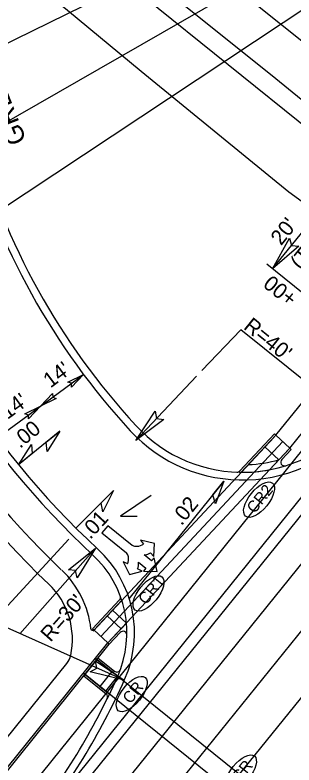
# Model space of a CAD drawing. Extents: x 1486489 to 1490134, y 497089 to 500876.
# Drawn here: x 1488642 to 1488715.1, y 499048.4 to 499245.3 of the extents above; entities that cross this region are included whole.
import ezdxf

# ---------------------------------------------------------------- set-up
doc = ezdxf.new("R2010")
doc.units = 0
for name, color, linetype in [('DEV PRELIMINARY STAMP CELL', 7, 'Continuous'), ('Gray Area Fill Shapes', 7, 'Continuous'), ('Pattern 5', 7, 'Continuous'), ('Prop DSN Text', 7, 'Continuous'), ('Prop Guardrail Anchor Unit CELL', 7, 'Continuous'), ('Prop Horizontal Alignment Station Label', 7, 'Continuous'), ('Prop North Arrow NAD83 for Plan Sheets CELL', 7, 'Continuous'), ('Prop Rem of Exist Asph Pvmt', 7, 'Continuous'), ('Prop Text', 7, 'Continuous'), ('Prop WCC CELL', 7, 'Continuous'), ('Scratch_Level_0', 7, 'Continuous'), ('Scratch_Level_5', 7, 'Continuous'), ('Sheet Block Revision CELL', 7, 'Continuous'), ('Sheet Block Title CELL', 7, 'Continuous'), ('Sheet Cutting Line CELL', 7, 'Continuous'), ('Sheet Data Field CELL', 7, 'Continuous'), ('Sheet Plan CELL', 7, 'Continuous'), ('Sheet Plot Border Inside CELL', 7, 'Continuous'), ('Sheet Plot Border Outside CELL', 7, 'Continuous'), ('Sheet Sticker Exception Certification CELL', 7, 'Continuous')]:
    doc.layers.add(name, color=color, linetype=linetype)

msp = doc.modelspace()

# ---------------------------------------------------------------- linework, layer by layer
at = {"layer": 'DEV PRELIMINARY STAMP CELL'}
for p, q in [((1488709.54, 499178.58), (1488722.09, 499194.15)), ((1488742.52, 499151.98), (1488707.98, 499179.84)), ((1488653.77, 499136.03), (1488642.91, 499127.2)), ((1488696.73, 499122.88), (1488671.81, 499091.97)), ((1488657.96, 499110.53), (1488667.84, 499120.45))]:
    msp.add_line(p, q, dxfattribs=at)
for points in [[(1488716.39, 499184.61), (1488709.54, 499178.58), (1488713.97, 499186.63), (1488714.49, 499184.73)], [(1488653.77, 499136.03), (1488650.38, 499130.69), (1488650.18, 499133.11)], [(1488642.91, 499127.2), (1488646.3, 499132.53), (1488646.5, 499130.12)], [(1488696.73, 499122.88), (1488694.52, 499116.95), (1488693.83, 499119.28)], [(1488667.84, 499120.45), (1488665.02, 499114.79), (1488664.58, 499117.17)]]:
    msp.add_lwpolyline(points, close=True, dxfattribs=at)
at = {"layer": 'Pattern 5'}
for p, q in [((1488708.74, 499125.87), (1488711.18, 499128.49)), ((1488703.19, 499127.24), (1488701.29, 499125.2)), ((1488667.55, 499089.02), (1488666.18, 499087.56)), ((1488671.2, 499085.62), (1488667.55, 499089.02)), ((1488666.18, 499087.56), (1488669.83, 499084.15)), ((1488669.83, 499084.15), (1488671.2, 499085.62))]:
    msp.add_line(p, q, dxfattribs=at)
msp.add_lwpolyline([(1488669.83, 499084.15), (1488669.83, 499084.15)], dxfattribs=at)
for radius, start, end in [(36, 272.4835, 285.3858), (38, 269.494, 280.7817)]:
    msp.add_arc((1488701.63, 499163.2), radius, start, end, dxfattribs=at)
at = {"layer": 'Prop DSN Text'}
for p, q in [((1488775.29, 499304.32), (1488416.25, 499127.99)), ((1488432.18, 499098.05), (1488779.08, 499297.19)), ((1488783.32, 499290.32), (1488450, 499069.19)), ((1488566.47, 498943.86), (1488817.57, 499255.22))]:
    msp.add_line(p, q, dxfattribs=at)
at = {"layer": 'Prop Horizontal Alignment Station Label'}
for p, q in [((1488710.38, 499134.95), (1488753.3, 499188.25)), ((1488714.03, 499131.55), (1488719.53, 499138.4)), ((1488710.38, 499134.95), (1488701.29, 499125.2)), ((1488714.03, 499131.55), (1488710.38, 499134.95)), ((1488711.18, 499128.49), (1488707.53, 499131.9)), ((1488714.03, 499131.55), (1488708.74, 499125.87)), ((1488662.74, 499083.86), (1488669.96, 499091.61)), ((1488671.2, 499085.62), (1488667.55, 499089.02)), ((1488669.83, 499084.15), (1488666.18, 499087.56)), ((1488666.32, 499080.39), (1488671.2, 499085.62)), ((1488666.33, 499080.4), (1488662.68, 499083.81)), ((1488627.75, 499032.57), (1488666.32, 499080.39)), ((1488623.86, 499035.7), (1488655.57, 499075.03))]:
    msp.add_line(p, q, dxfattribs=at)
for centre, radius, start, end in [((1488809.02, 499262.12), 224.5, 195.2846, 226.3706), ((1488809.02, 499262.12), 229.5, 195.2846, 226.422), ((1488701.63, 499163.2), 36, 272.4835, 285.3858), ((1488637.03, 499081.37), 25, 6.3813, 46.422), ((1488637.03, 499081.37), 20, 347.6839, 46.422), ((1488662.37, 499084.2), 0.5, 186.3813, 316.995), ((1488651.68, 499078.17), 5, 321.1156, 347.6839)]:
    msp.add_arc(centre, radius, start, end, dxfattribs=at)
at = {"layer": 'Prop North Arrow NAD83 for Plan Sheets CELL'}
for p, q in [((1488710.02, 499135.29), (1488700.93, 499125.55)), ((1488710.38, 499134.95), (1488710.02, 499135.29)), ((1488714.03, 499131.55), (1488714.4, 499131.21)), ((1488714.4, 499131.21), (1488711.94, 499128.57)), ((1488662.32, 499084.15), (1488669.37, 499091.71)), ((1488662.32, 499084.15), (1488662.68, 499083.81)), ((1488666.7, 499080.06), (1488669.58, 499083.15)), ((1488666.33, 499080.4), (1488666.7, 499080.06)), ((1488628.14, 499032.25), (1488666.71, 499080.08))]:
    msp.add_line(p, q, dxfattribs=at)
for centre, start, end in [((1488712.67, 499127.89), 136.9971, 287.3568), ((1488700.2, 499126.23), 267.7855, 316.995), ((1488668.64, 499092.39), 316.995, 20.3225), ((1488670.31, 499082.47), 358.8535, 136.9971)]:
    msp.add_arc(centre, 1, start, end, dxfattribs=at)
at = {"layer": 'Prop Rem of Exist Asph Pvmt'}
for points in [[(1488755.4, 499195.95), (1488744.07, 499202.68), (1488725.99, 499215.74), (1488710.36, 499228.49), (1488687.96, 499246.41), (1488668.5, 499262.14), (1488648.61, 499278.49), (1488630.4, 499293.26), (1488610.04, 499310.33), (1488591.6, 499325.39), (1488586.28, 499329.49), (1488591.25, 499319.52)], [(1488609.01, 499284.22), (1488609.63, 499282.52), (1488611.82, 499282.27), (1488614.97, 499280.23), (1488636.47, 499262.18), (1488655.78, 499246.53), (1488675.03, 499230.53), (1488696.14, 499213.29), (1488713.83, 499198.84), (1488732.27, 499185.48), (1488742.82, 499178.43)]]:
    msp.add_lwpolyline(points, dxfattribs=at)
at = {"layer": 'Prop Text'}
for p, q in [((1488662.43, 499083.53), (1488709.91, 499134.44)), ((1488666.32, 499080.39), (1488713.8, 499131.3)), ((1488711.66, 499037.18), (1488663.07, 499076.36)), ((1488709.75, 499032.29), (1488659.93, 499072.47))]:
    msp.add_line(p, q, dxfattribs=at)
at = {"layer": 'Prop WCC CELL'}
for centre in [(1488705.98, 499118.02), (1488676.98, 499093.39)]:
    msp.add_ellipse(centre, major_axis=(3.52, 4.36), ratio=0.462467, dxfattribs=at)
at = {"layer": 'Scratch_Level_0'}
for p, q in [((1488691, 499151.89), (1488701.17, 499162.63)), ((1488732.3, 499137.52), (1488701.17, 499162.63)), ((1488673.67, 499133.58), (1488689.59, 499150.4)), ((1488712.21, 499133.25), (1488664.51, 499082.1)), ((1488663.09, 499105.32), (1488643.24, 499082.83)), ((1488670.63, 499070.6), (1488632.82, 499087.48))]:
    msp.add_line(p, q, dxfattribs=at)
for points in [[(1488680.98, 499139.05), (1488673.67, 499133.58), (1488678.73, 499141.25), (1488679.1, 499139.32)], [(1488655.97, 499099.6), (1488663.09, 499105.32), (1488658.3, 499097.47), (1488657.86, 499099.39)], [(1488663.04, 499075.69), (1488670.63, 499070.6), (1488661.71, 499072.83), (1488663.42, 499073.82)]]:
    msp.add_lwpolyline(points, close=True, dxfattribs=at)
at = {"layer": 'Scratch_Level_5'}
for centre, radius, start, end in [((1488809.02, 499262.12), 184, 195.2846, 222.6475), ((1488809.02, 499262.12), 216, 195.2846, 227.2261), ((1488701.63, 499163.2), 38, 222.6475, 321.1156), ((1488643.32, 499083.01), 28, 336.027, 47.2261), ((1488506.26, 499143.96), 178, 321.1156, 336.027)]:
    msp.add_arc(centre, radius, start, end, dxfattribs=at)
at = {"layer": 'Sheet Block Revision CELL'}
for p, q in [((1488663.07, 499076.36), (1488668.91, 499071.65)), ((1488663.46, 499076.05), (1488663.77, 499076.44)), ((1488663.77, 499076.44), (1488668.04, 499072.99)), ((1488663.46, 499076.05), (1488660.32, 499072.15)), ((1488659.93, 499072.47), (1488666.75, 499066.97)), ((1488667.35, 499072.91), (1488664.21, 499069.01)), ((1488668.91, 499071.65), (1488667.35, 499072.91)), ((1488660.32, 499072.15), (1488660.01, 499071.76)), ((1488660.01, 499071.76), (1488665.9, 499067.01)), ((1488665.77, 499067.76), (1488668.91, 499071.65)), ((1488664.21, 499069.01), (1488665.77, 499067.76))]:
    msp.add_line(p, q, dxfattribs=at)
msp.add_lwpolyline([(1488677.72, 499119.07), (1488669.61, 499113.66), (1488674, 499113.66)], dxfattribs=at)
for centre, start, end in [((1488668.67, 499073.77), 231.1156, 340.3984), ((1488665.28, 499066.23), 333.9506, 51.1156)]:
    msp.add_arc(centre, 1, start, end, dxfattribs=at)
for centre in [(1488672.58, 499066.98), (1488701.24, 499046.37)]:
    msp.add_ellipse(centre, major_axis=(3.52, 4.36), ratio=0.462467, dxfattribs=at)
at = {"layer": 'Sheet Block Title CELL'}
for p, q in [((1488646.37, 499030.96), (1488732.3, 499137.52)), ((1488690.38, 499032.96), (1488772.04, 499134.22)), ((1488656.94, 499009.02), (1488754.24, 499129.68)), ((1488648.38, 499015.93), (1488739.4, 499128.8))]:
    msp.add_line(p, q, dxfattribs=at)
at = {"layer": 'Sheet Cutting Line CELL'}
for p, q in [((1488648.69, 499142.55), (1488659.91, 499150.92)), ((1488637.34, 499134.36), (1488648.69, 499142.55))]:
    msp.add_line(p, q, dxfattribs=at)
at = {"layer": 'Sheet Data Field CELL'}
msp.add_line((1488639.14, 499089.21), (1488656.06, 499107.62), dxfattribs=at)
at = {"layer": 'Sheet Plan CELL'}
for p, q in [((1488632.83, 499306.48), (1488944.2, 499055.38)), ((1488933.52, 499042.15), (1488622.16, 499293.25)), ((1488574.59, 498937.3), (1488825.69, 499248.67))]:
    msp.add_line(p, q, dxfattribs=at)
at = {"layer": 'Sheet Plot Border Inside CELL'}
for p, q in [((1488666.29, 499111.18), (1488664.78, 499109.29)), ((1488672.71, 499106.02), (1488666.29, 499111.18)), ((1488664.78, 499109.29), (1488671.24, 499104.1)), ((1488678.54, 499106.5), (1488674.87, 499107.39)), ((1488674.87, 499107.39), (1488675.67, 499106.35)), ((1488678.34, 499103.06), (1488678.54, 499106.5)), ((1488677.54, 499104.09), (1488678.34, 499103.06)), ((1488677.81, 499101.93), (1488675.83, 499103.52)), ((1488678.44, 499102.72), (1488677.81, 499101.93)), ((1488679.27, 499099.16), (1488678.44, 499102.72)), ((1488671.52, 499101.18), (1488670.33, 499101.73)), ((1488670.33, 499101.73), (1488672.02, 499098.38)), ((1488674.35, 499101.6), (1488676.29, 499100.04)), ((1488676.29, 499100.04), (1488675.66, 499099.25)), ((1488672.02, 499098.38), (1488675.31, 499099.29)), ((1488675.31, 499099.29), (1488674.12, 499099.84)), ((1488675.66, 499099.25), (1488679.27, 499099.16))]:
    msp.add_line(p, q, dxfattribs=at)
for centre, major_axis, start_param, end_param in [((1488673.3, 499107.79), (1.77, -1.42), 4.994449, 5.60123), ((1488673.02, 499109.32), (3.12, -2.5), 5.540317, 6.08015), ((1488669.61, 499103.19), (1.77, -1.42), 0.681955, 1.257878), ((1488674.88, 499107.03), (3.12, -2.5), 5.547466, 6.086593), ((1488668.06, 499103.13), (3.12, -2.5), 0.198105, 0.742869), ((1488670.69, 499101.81), (3.12, -2.5), 0.191642, 0.728793)]:
    msp.add_ellipse(centre, major_axis=major_axis, ratio=0.8, start_param=start_param, end_param=end_param, dxfattribs=at)
at = {"layer": 'Sheet Plot Border Outside CELL'}
for points in [[(1488655.84, 499148.85), (1488659.91, 499150.92), (1488656.76, 499147.58), (1488656.75, 499148.56)], [(1488652.76, 499144.62), (1488648.69, 499142.55), (1488651.84, 499145.9), (1488651.86, 499144.91)], [(1488644.59, 499140.55), (1488648.69, 499142.55), (1488645.49, 499139.26), (1488645.49, 499140.24)]]:
    msp.add_lwpolyline(points, close=True, dxfattribs=at)
at = {"layer": 'Sheet Sticker Exception Certification CELL'}
for centre, radius, start, end in [((1488809.02, 499262.12), 186, 195.2846, 222.6475), ((1488809.02, 499262.12), 214, 195.2846, 227.2261), ((1488701.63, 499163.2), 40, 222.6475, 321.1156), ((1488643.32, 499083.01), 30, 336.027, 47.2261), ((1488506.26, 499143.96), 180, 321.1156, 336.027)]:
    msp.add_arc(centre, radius, start, end, dxfattribs=at)

# ---------------------------------------------------------------- texts
at = {"layer": 'DEV PRELIMINARY STAMP CELL'}
for s, rotation, p in [("20'", 51.1156, (1488711.77, 499184.54)), ('(TYP)', 51.1156, (1488716.91, 499178.16)), ('.00', 39.0835, (1488643.27, 499131.32)), ('.01', 47.4135, (1488661.72, 499107.39))]:
    msp.add_text(s, height=4, rotation=rotation, dxfattribs=at).set_placement(p)
at = {"layer": 'Gray Area Fill Shapes'}
for s, rotation, p in [('+00', 141.1755, (1488716.34, 499171.54)), ('.02', 51.1156, (1488685.65, 499111.01))]:
    msp.add_text(s, height=4, rotation=rotation, dxfattribs=at).set_placement(p)
at = {"layer": 'Prop Guardrail Anchor Unit CELL'}
msp.add_text('GREU TL-2', height=5, rotation=111.3982, dxfattribs=at).set_placement((1488645.06, 499212.3))
at = {"layer": 'Prop WCC CELL'}
for s, p in [('CR2', (1488704.81, 499114.21)), ('CR1', (1488676.34, 499090.25))]:
    msp.add_text(s, height=3, rotation=51.1156, dxfattribs=at).set_placement(p)
at = {"layer": 'Scratch_Level_0'}
for s, rotation, p in [("R=40'", 321.1156, (1488701.68, 499163.04)), ("R=30'", 48.5528, (1488651.28, 499080.44))]:
    msp.add_text(s, height=4, rotation=rotation, dxfattribs=at).set_placement(p)
at = {"layer": 'Sheet Block Revision CELL'}
for p in [(1488672.25, 499064.22), (1488700.91, 499043.61)]:
    msp.add_text('CR', height=3, rotation=51.1156, dxfattribs=at).set_placement(p)
at = {"layer": 'Sheet Cutting Line CELL'}
for rotation, p in [(36.7132, (1488651.27, 499147.19)), (35.8006, (1488639.99, 499138.96))]:
    msp.add_text("14'", height=4, rotation=rotation, dxfattribs=at).set_placement(p)

doc.saveas('drawing.dxf')
